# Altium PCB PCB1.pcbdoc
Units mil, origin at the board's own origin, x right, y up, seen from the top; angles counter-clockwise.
Board outline 8195 x 5475 mil, 2 copper layers (Top Layer, Bottom Layer), stack 62.206 mil thick; 63 components, 65 nets, 212 pads, 6 vias.
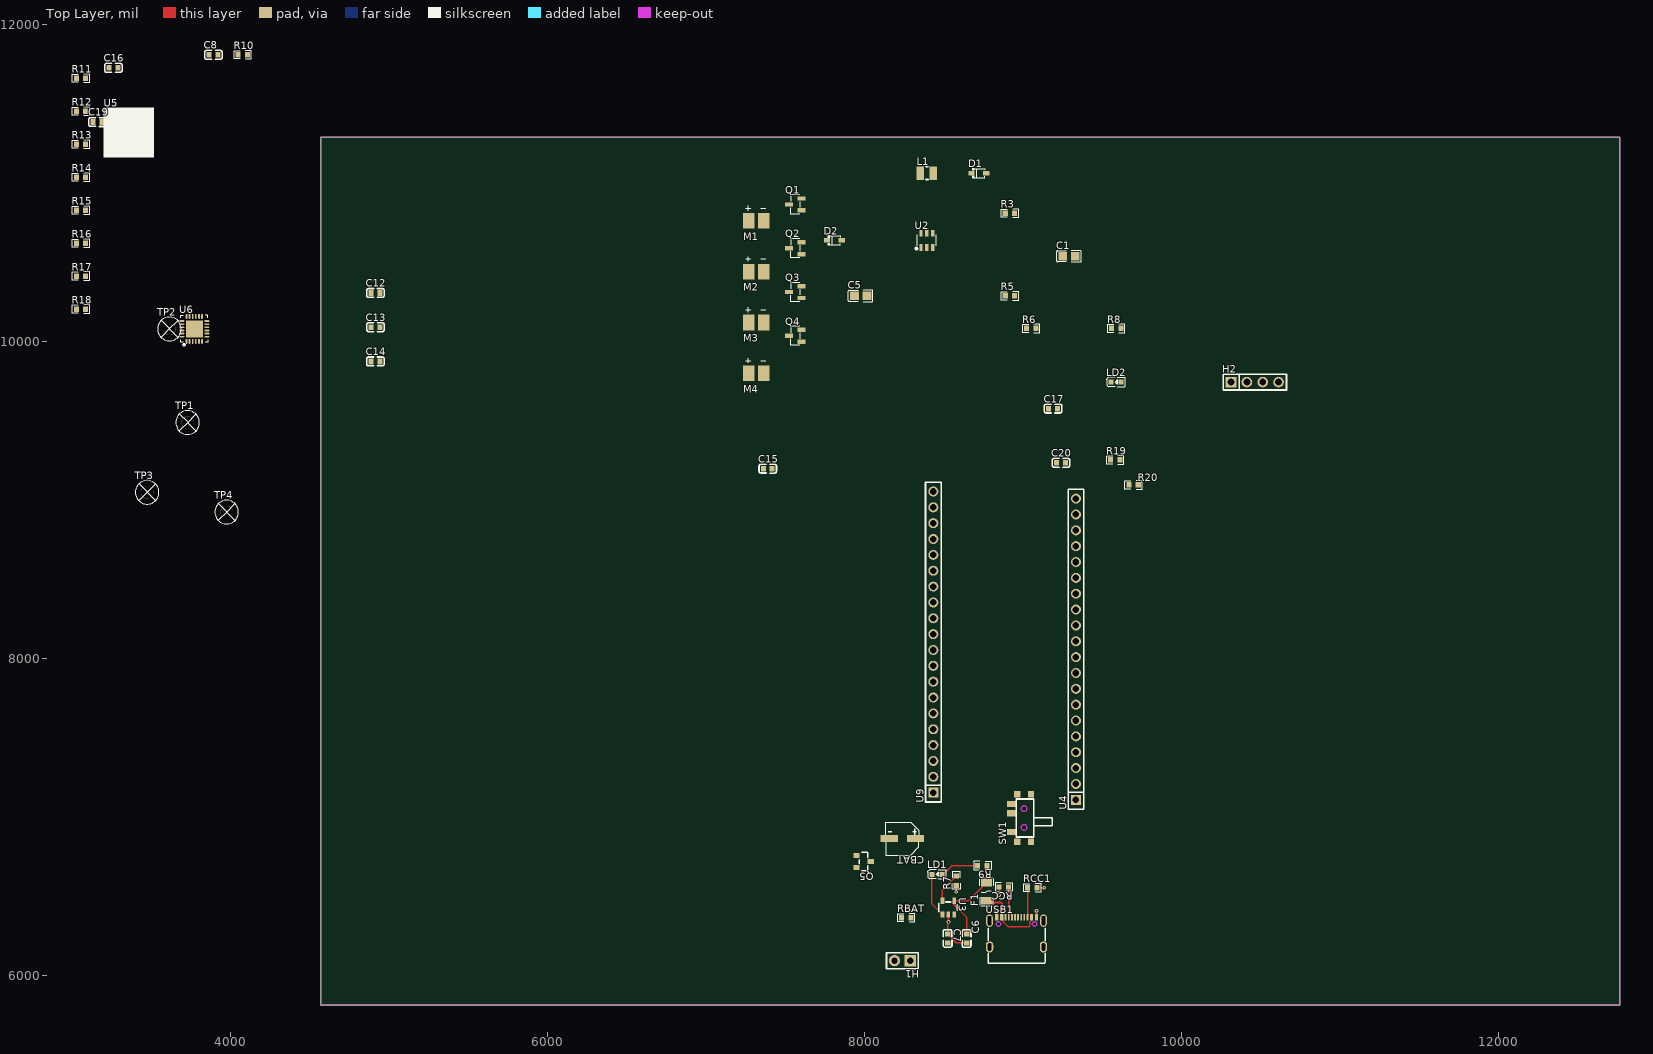
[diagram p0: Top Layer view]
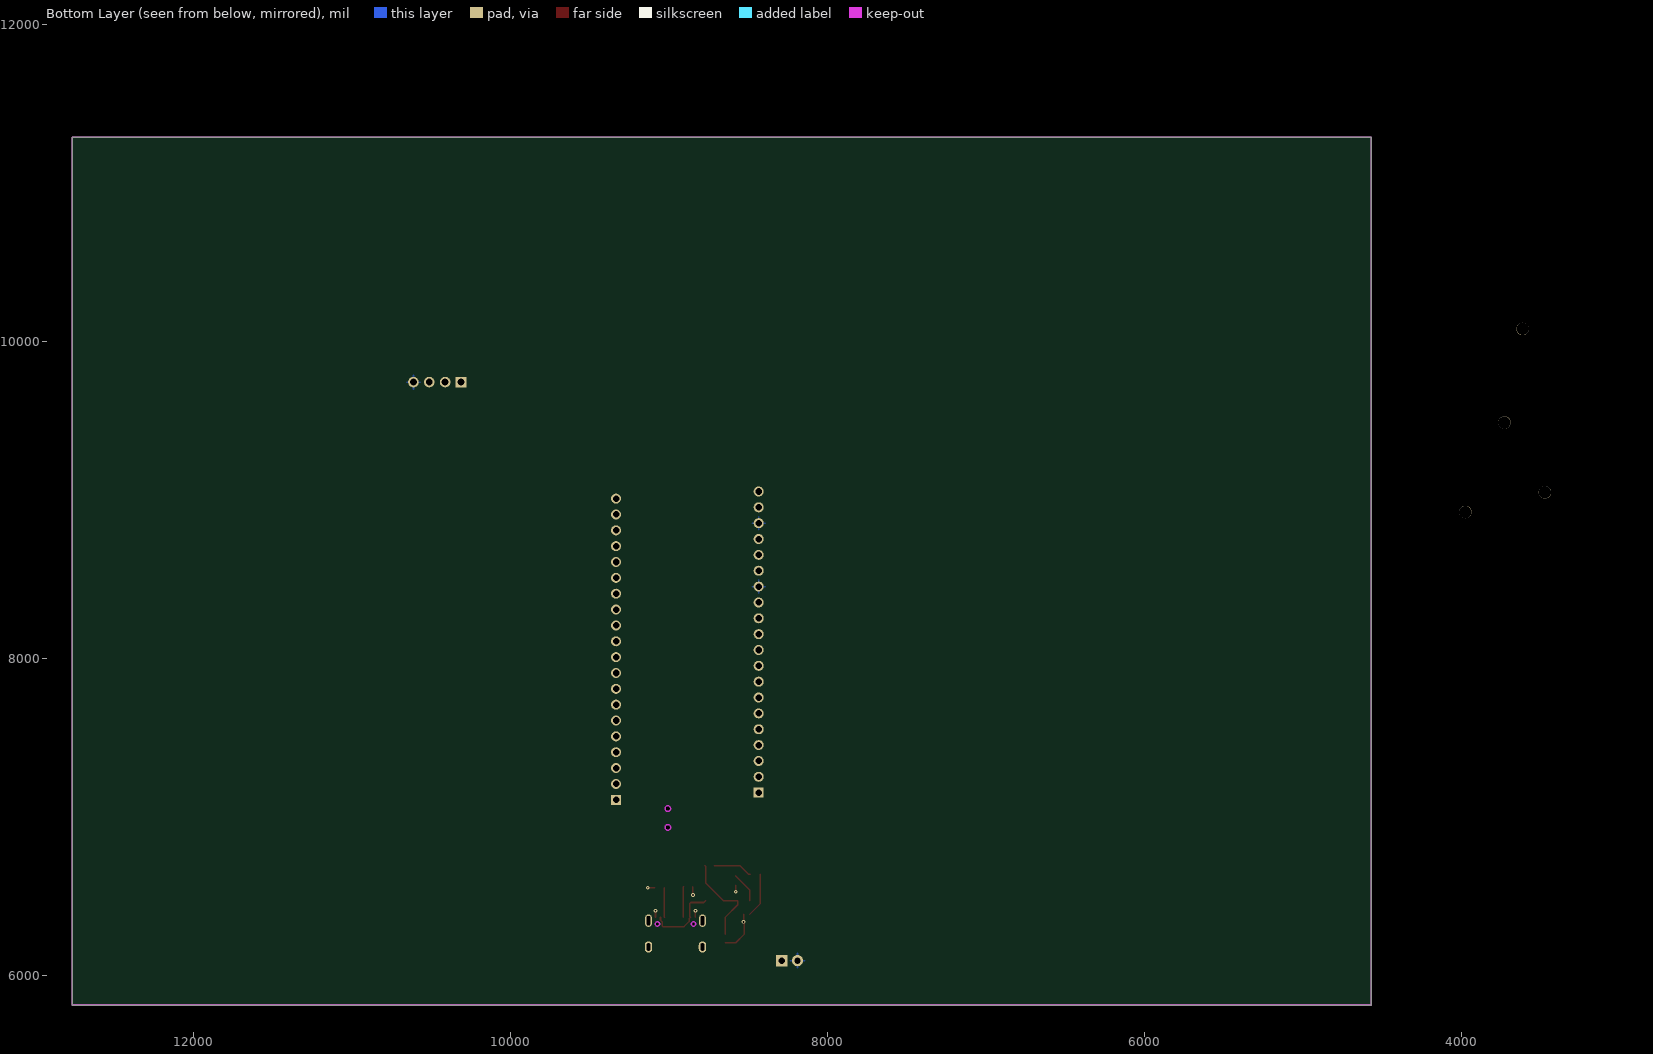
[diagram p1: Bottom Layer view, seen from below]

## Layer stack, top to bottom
Top Solder Mask Layer: solder mask 0.394, Dk 3.3
Top Layer: signal copper 1.379
Dielectric1: surface 59.449, FR4, Dk 4.5
Bottom Layer: signal copper 1.378
Bottom Solder Mask Layer: solder mask 0.394, Dk 3.3

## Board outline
4566.53,11290 4566.53,5815 12761.53,5815 12761.53,11290

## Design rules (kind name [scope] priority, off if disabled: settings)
BoardOutlineClearance copperThickness2oz_1 [All] p2 off: genericclearance=7.99 ignorepadtopadclearanceinfootprint=FALSE except(0: Arc-SplitContinuation Track-SplitContinuation SMDPad-SplitContinuation THPad-SplitContinuation Via-SplitContinuation Fill-SplitContinuation Region-SplitContinuation Poly-SplitContinuation Text-SplitContinuation Hole-SplitContinuation; 5.98: Arc-CutoutEdge SMDPad-CutoutEdge THPad-CutoutEdge Via-CutoutEdge Fill-CutoutEdge Region-CutoutEdge Text-CutoutEdge; 6.93: Hole-OutlineEdge Hole-CutoutEdge; 10: Poly-OutlineEdge Poly-CutoutEdge; 11.81: Arc-OutlineEdge Track-OutlineEdge SMDPad-OutlineEdge THPad-OutlineEdge Via-OutlineEdge Fill-OutlineEdge Region-OutlineEdge Text-OutlineEdge Track-CutoutEdge)
BoardOutlineClearance copperThickness1oz_1 [All] p4: genericclearance=4.02 ignorepadtopadclearanceinfootprint=FALSE except(0: Arc-SplitContinuation Track-SplitContinuation SMDPad-SplitContinuation THPad-SplitContinuation Via-SplitContinuation Fill-SplitContinuation Region-SplitContinuation Poly-SplitContinuation Text-SplitContinuation Hole-SplitContinuation; 6: SMDPad-CutoutEdge THPad-CutoutEdge Via-CutoutEdge Fill-CutoutEdge Region-CutoutEdge Text-CutoutEdge; 6.93: Hole-OutlineEdge Hole-CutoutEdge; 10: Poly-OutlineEdge Poly-CutoutEdge; 11.8: Arc-OutlineEdge Track-OutlineEdge SMDPad-OutlineEdge THPad-OutlineEdge Via-OutlineEdge Fill-OutlineEdge Region-OutlineEdge Text-OutlineEdge; 11.81: Arc-CutoutEdge Track-CutoutEdge)
Clearance copperThickness2oz [All] p1 off: gap=7.99 ignorepadtopadclearanceinfootprint=FALSE except(5.98: SMDPad-Track SMDPad-SMDPad THPad-Track SMDPad-THPad THPad-THPad Track-Via SMDPad-Via THPad-Via Via-Via Fill-Track Region-Track Fill-SMDPad Region-SMDPad Fill-THPad Region-THPad Fill-Via Region-Via Fill-Fill Fill-Region Region-Region Arc-Track Arc-SMDPad Arc-THPad Arc-Via Fill-Arc Region-Arc Arc-Arc Text-Track SMDPad-Text Text-THPad Text-Via Fill-Text Region-Text Arc-Text Text-Text; 6.93: Hole-Track Hole-SMDPad Hole-THPad Hole-Via Fill-Hole Region-Hole Hole-Arc Hole-Text; 10: Poly-Track Poly-SMDPad Poly-THPad Poly-Via Poly-Fill Poly-Region Poly-Poly Poly-Arc Poly-Text Poly-Hole)
Clearance copperThickness1oz [All] p3: gap=4.02 ignorepadtopadclearanceinfootprint=FALSE except(5.98: SMDPad-Track SMDPad-SMDPad THPad-Track SMDPad-THPad THPad-THPad Track-Via SMDPad-Via THPad-Via Via-Via Fill-Track Region-Track Fill-SMDPad Region-SMDPad Fill-THPad Region-THPad Fill-Via Region-Via Fill-Fill Fill-Region Region-Region; 6: Arc-Track Arc-SMDPad Arc-THPad Arc-Via Fill-Arc Region-Arc Arc-Arc Text-Track SMDPad-Text Text-THPad Text-Via Fill-Text Region-Text Arc-Text Text-Text; 6.93: Hole-Track Hole-SMDPad Hole-THPad Hole-Via Fill-Hole Region-Hole Hole-Arc Hole-Text; 10: Poly-Track Poly-SMDPad Poly-THPad Poly-Via Poly-Fill Poly-Region Poly-Poly Poly-Arc Poly-Text Poly-Hole)
Creepage creepage [All] p1: checkdistance=0 ignoreinternallayers=TRUE applytopolygonpour=TRUE
DiffPairsRouting differentialPair [All] p1: maxlimit=6 minlimit=6 mostfreqgap=6 toplayer_minwidth=5 toplayer_prefwidth=10 toplayer_maxwidth=100 toplayer_mingap=6 toplayer_prefgap=6 toplayer_maxgap=6 bottomlayer_minwidth=5 bottomlayer_prefwidth=10 bottomlayer_maxwidth=100 bottomlayer_mingap=6 bottomlayer_prefgap=6 bottomlayer_maxgap=6 maxuncoupledlength=10
HoleToHoleClearance otherClearance [All] p1: gap=11.81 allowstackedmicrovias=TRUE
Length netLength [All] p1: minlimit=0 maxlimit=0
MatchedLengths netLengthTolerance [All] p1: tolerance=1000
PasteMaskExpansion pasteMaskExpansion [All] p1: expansion=0
PlaneConnect innerPlane [All] p1: planeconnectstyle=Relief reliefexpansion=20 reliefentries=4 reliefconductorwidth=10 reliefairgap=10
PolygonConnect copperRegion [(InNet('GND'))] p1: connectstyle=Relief reliefconductorwidth=10 reliefentries=4 polygonreliefangle="90 Angle" airgapwidth=10 via.connectstyle=Relief via.reliefconductorwidth=10 via.reliefentries=4 via.polygonreliefangle="90 Angle" via.airgapwidth=10
RoutingVias viaSize [All] p1: holewidth=12.01 width=24.02 viastyle="Through Hole" minholewidth=11.81 minwidth=19.68 maxholewidth=248.03 maxwidth=393.7
SolderMaskExpansion solderMaskExpansion [IsVia] p1: expansion=-1000 istentingtop=TRUE
SolderMaskExpansion solderMaskExpansion [All] p2: expansion=2 istentingtop=FALSE
Width copperThickness2oz_2 [All] p1 off: maxlimit=100 minlimit=8 preferedwidth=10
Width copperThickness1oz_2 [All] p2: maxlimit=100 minlimit=5 preferedwidth=10

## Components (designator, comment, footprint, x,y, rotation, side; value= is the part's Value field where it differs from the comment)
C1 "22uF" C0805 9287.35,10539.06 r0 top
C5 "22uF" C0805 7973.57,10289.06 r0 top
C6 "4.7uF" C0603 8641.53,6235 r90 top
C7 "10uF" C0603 8521.53,6235 r270 top
C8 "100nF" C0603 3890.05,11809.78 r0 top
C12 "4.7uF" C0603 4912.48,10307.56 r0 top
C13 "4.7uF" C0603 4912.48,10091.44 r0 top
C14 "4.7uF" C0603 4912.48,9875.32 r0 top
C15 "4.7uF" C0603 7387.48,9199.2 r0 top
C16 "100nF" C0603 3258.9,11727.92 r0 top
C17 "100nF" C0603 9187.35,9577.92 r0 top
C19 "10nF" C0603 3158.9,11385.9 r0 top
C20 "2.2nF" C0603 9237.35,9235.9 r0 top
CBAT "10uF" CAP-SMD_BD5.0-L5.3-W5.3-LS6.0-FD 8236.53,6865 r180 top
D1 "1N5819WS" SOD-323_L1.8-W1.3-LS2.5-RD 8719.18,11063.15 r0 top
D2 "1N5819WS" SOD-323_L1.8-W1.3-LS2.5-RD 7807.73,10639.06 r0 top
F1 "JK-nSMD100/16V" F1206 8766.53,6530 r90 top
H1 "" HDR-TH_2P-P2.54-V-M-1 8236.53,6095 r180 top
H2 "" HDR-TH_4P-P2.54-V-M 10459.63,9745.28 r0 top
L1 "10uH" IND-SMD_L2.5-W2.0 8390.8,11063.15 r0 top
LD1 "" LED_0603 8456.53,6640 r0 top
LD2 "" LED_0603 9585.63,9745.28 r0 top
M1 "8520" 8520电机接口 7314.21,10762.64 r0 top
M2 "8520" 8520电机接口 7314.21,10441.99 r0 top
M3 "8520" 8520电机接口 7314.21,10121.34 r0 top
M4 "8520" 8520电机接口 7314.21,9800.69 r0 top
Q1 "SI2302" SOT-23-3_L2.9-W1.3-P1.90-LS2.4-BR 7560.86,10865.74 r0 top
Q2 "SI2302" SOT-23-3_L2.9-W1.3-P1.90-LS2.4-BR 7560.86,10589.57 r0 top
Q3 "SI2302" SOT-23-3_L2.9-W1.3-P1.90-LS2.4-BR 7560.86,10313.39 r0 top
Q4 "SI2302" SOT-23-3_L2.9-W1.3-P1.90-LS2.4-BR 7560.86,10037.22 r0 top
Q5 "AO3401A" SOT-23_L2.9-W1.3-P1.90-LS2.4-BR 7991.53,6720 r180 top
R3 "75kΩ" R0603 8915.05,10809.77 r0 top
R5 "10K" R0603 8915.05,10289.06 r0 top
R6 "200K" R0603 9049.79,10083.66 r0 top
R7 "2K" R0603 8576.53,6600 r90 top
R8 "10K" R0603 9585.63,10083.66 r0 top
R9 "10K" R0603 8741.53,6695 r180 top
R10 "100K" R0603 4074.79,11809.78 r0 top
R11 "100" R0603 3054.53,11661.86 r0 top
R12 "100" R0603 3054.53,11453.85 r0 top
R13 "100" R0603 3054.53,11245.83 r0 top
R14 "100" R0603 3054.53,11037.82 r0 top
R15 "10K" R0603 3054.53,10829.8 r0 top
R16 "10K" R0603 3054.53,10621.78 r0 top
R17 "10K" R0603 3054.53,10413.77 r0 top
R18 "10K" R0603 3054.53,10205.75 r0 top
R19 "4.7K" R0603 9579.87,9254.25 r0 top
R20 "4.7K" R0603 9694.87,9096.55 r0 top
RBAT "100K" R0603 8261.53,6365 r0 top
RCC "5.1K" R0603 8876.53,6560 r180 top
RCC1 "5.1K" R0603 9056.53,6555 r0 top
SW1 "SK-3296S-01-L1" SW-SMD_3P-P1.50_L2.7-W6.6 8986.53,6995 r90 top
TP1 "" M2螺丝 3726.53,9490 r0 top
TP2 "" M2螺丝 3612.47,10080.27 r0 top
TP3 "" M2螺丝 3471.53,9050 r0 top
TP4 "" M2螺丝 3972.98,8925.27 r0 top
U2 "MT3608" SOT-23-6_L2.9-W1.6-P0.95-LS2.8-BL 8390.8,10639.06 r0 top
U3 "LTH7" SOT-23-5_L2.9-W1.6-P0.95-LS2.8-BR 8526.53,6430 r270 top
U4 "排针左" HDR-TH_LAIL-PM2.54-20P-L 9331.53,8060 r90 top
U5 "" JLC-QRCODE-8x8 3356.53,11320 r0 top
U6 "MPU-6050" QFN-24_L4.0-W4.0-P0.50-BL-EP2.7 3769.18,10081.07 r0 top
U9 "排针右" HDR-TH_LAIL-PM2.54-20P-L 8431.53,8105 r90 top
USB1 "TYPE-C 16PIN 2MD(073)" USB-C-SMD_TYPE-C-6PIN-2MD-073 8956.53,6275 r0 top

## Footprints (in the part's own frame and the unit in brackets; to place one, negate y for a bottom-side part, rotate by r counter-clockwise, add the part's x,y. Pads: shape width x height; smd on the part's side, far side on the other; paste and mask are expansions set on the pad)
8520电机接口 [mm]
  rect 1.8x2.5 smd: 1(-1.2,0) 2(1.2,0)
  silkscreen extent -1.65,1.65 1.51,2.41
C0603 [mm]
  rect 0.8x0.9 smd: 1(-0.7,0) 2(0.7,0)
  silkscreen extent -1.41,-0.71 1.39,0.72
C0805 [mm]
  rect 1.41x1.35 smd paste-100 mask+0.051: 1(-1,0) 2(1,0)
  silkscreen extent -1.96,-0.9 1.96,0.9
CAP-SMD_BD5.0-L5.3-W5.3-LS6.0-FD [mm]
  rect 2.8x1.1 smd: 1(-2.1,0) 2(2.1,0)
  silkscreen extent -2.66,-2.62 2.66,2.65
F1206 [mm]
  rect 1.19x1.728 smd: 1(-1.445,0) 2(1.445,0)
  silkscreen extent -2.27,-1.09 2.27,1.09
HDR-TH_2P-P2.54-V-M-1 [mm]
  rect 1.8x1.8 hole 1: 1(-1.27,0)
  round 1.8 hole 1: 2(1.27,0)
  silkscreen extent -2.54,-1.27 2.54,1.27
HDR-TH_4P-P2.54-V-M [mm]
  rect 1.7x1.7 hole 1.1: 1(-3.81,0)
  round 1.7 hole 1.1: 2(-1.27,0) 3(1.27,0) 4(3.81,0)
  silkscreen extent -5.08,-1.27 5.08,1.27
HDR-TH_LAIL-PM2.54-20P-L [mm]
  rect 1.6x1.6 hole 1.05 paste+0 mask+0.051: 1(-24.13,0)
  round 1.6 hole 1.05 paste+0 mask+0.051: 2(-21.59,0) 3(-19.05,0) 4(-16.51,0) 5(-13.97,0) 6(-11.43,0) 7(-8.89,0) 8(-6.35,0) 9(-3.81,0) 10(-1.27,0) 11(1.27,0) 12(3.81,0) 13(6.35,0) 14(8.89,0) 15(11.43,0) 16(13.97,0) 17(16.51,0) 18(19.05,0) 19(21.59,0) 20(24.13,0)
  silkscreen extent -25.63,-1.25 25.64,1.25
IND-SMD_L2.5-W2.0 [mm]
  rect 1.2x2.2 smd: 1(1.028,0) 2(-1.028,0)
  silkscreen extent -0.2,-1.02 0.2,1.02
JLC-QRCODE-8x8 [mil]
  silkscreen extent -157,-157 157,157
LED_0603 [mil]
  rect 31.5x31.5 smd paste+0 mask+2: 1(-33.5,-0.4) 2(29.5,-0.2)
  silkscreen extent -61,-30 53,30
M2螺丝 [mm]
  round 2 hole 2: 1(0,0)
  silkscreen extent -1.9,-1.9 1.9,1.9
QFN-24_L4.0-W4.0-P0.50-BL-EP2.7 [mm]
  oval 0.28x0.8 smd paste-100 mask+0.05: 1(-1.25,-2) 2(-0.75,-2) 3(-0.25,-2) 4(0.25,-2) 5(0.75,-2) 6(1.25,-2) 13(1.25,2) 14(0.75,2) 15(0.25,2) 16(-0.25,2) 17(-0.75,2) 18(-1.242,2)
  oval 0.8x0.28 smd paste-100 mask+0.05: 7(2,-1.25) 8(2,-0.75) 9(2,-0.25) 10(2,0.25) 11(2,0.75) 12(2,1.25) 19(-2,1.25) 20(-2,0.75) 21(-2,0.25) 22(-2,-0.25) 23(-2,-0.75) 24(-2,-1.25)
  rect 2.7x2.7 smd paste-100 mask+0.05: 25(0.012,0)
  silkscreen extent -2.14,-2.79 2.16,2.15
R0603 [mil]
  rect 31.75x34.02 smd paste-3937.01 mask+2: 1(-29.66,0) 2(29.66,0)
  silkscreen extent -55,-26 55,26
SOD-323_L1.8-W1.3-LS2.5-RD [mm]
  rect 1x0.75 smd: 1(-1.173,0) 2(1.173,0)
  silkscreen extent -1.08,-0.8 0.9,0.8
SOT-23-3_L2.9-W1.3-P1.90-LS2.4-BR [mm]
  rect 1.25x0.7 smd: 1(1,-0.95) 2(1,0.95) 3(-1,0)
  silkscreen extent -0.73,-1.53 0.73,1.53
SOT-23-5_L2.9-W1.6-P0.95-LS2.8-BR [mm]
  rect 1x0.6 smd paste+0 mask+0.05: 1(1.1,-0.95) 2(1.1,0) 3(1.1,0.95) 4(-1.1,0.95) 5(-1.1,-0.95)
  silkscreen extent -0.89,-1.52 0.7,1.4
SOT-23-6_L2.9-W1.6-P0.95-LS2.8-BL [mil]
  rect 20.95x42.2 smd: 1(-37.4,-45.24) 2(0,-45.24) 3(37.4,-45.24) 4(37.4,45.24) 5(0,45.24) 6(-37.4,45.24)
  silkscreen extent -72,-57 61,35
SOT-23_L2.9-W1.3-P1.90-LS2.4-BR [mm]
  rect 1x0.8 smd: 1(1.15,-0.95) 2(1.15,0.95) 3(-1.15,0)
  silkscreen extent -0.7,-1.5 0.7,1.5
SW-SMD_3P-P1.50_L2.7-W6.6 [mm]
  rect 1x1 smd: 0(-3.8,-1.559) 0(-3.8,0.641) 0(3.8,-1.559) 0(3.8,0.641)
  rect 1x1.4 smd: 1(-2.25,1.559) 2(0.75,1.559) 3(2.25,1.559)
  Board Outline Layer circle w0.003: c-1.5,-0.459 r0.45
  Board Outline Layer circle w0.003: c1.5,-0.459 r0.45
  Board Outline Layer region: -1.5,-0.909 -1.695,-0.864 -1.852,-0.74 -1.939,-0.559 -1.939,-0.359 -1.852,-0.178 -1.695,-0.054 -1.5,-0.009 -1.5,-0.009 -1.305,-0.054 -1.148,-0.178 -1.061,-0.359 -1.061,-0.559 -1.148,-0.74 -1.305,-0.864 -1.5,-0.909
  Board Outline Layer region: -1.5,-0.909 -1.593,-0.899 -1.683,-0.87 -1.764,-0.823 -1.834,-0.76 -1.89,-0.684 -1.928,-0.598 -1.947,-0.506 -1.947,-0.412 -1.928,-0.32 -1.89,-0.234 -1.834,-0.158 -1.764,-0.095 -1.683,-0.048 -1.593,-0.019 -1.5,-0.009 -1.406,-0.019 -1.317,-0.048 -1.235,-0.095 -1.165,-0.158 -1.11,-0.234 -1.072,-0.32 -1.052,-0.412 -1.052,-0.506 -1.072,-0.598 -1.11,-0.684 -1.165,-0.76 -1.235,-0.823 -1.317,-0.87 -1.406,-0.899
  Board Outline Layer region: 1.5,-0.909 1.305,-0.864 1.148,-0.74 1.061,-0.559 1.061,-0.359 1.148,-0.178 1.305,-0.054 1.5,-0.009 1.5,-0.009 1.695,-0.054 1.852,-0.178 1.939,-0.359 1.939,-0.559 1.852,-0.74 1.695,-0.864 1.5,-0.909
  Board Outline Layer region: 1.5,-0.909 1.407,-0.899 1.317,-0.87 1.236,-0.823 1.166,-0.76 1.11,-0.684 1.072,-0.598 1.053,-0.506 1.053,-0.412 1.072,-0.32 1.11,-0.234 1.166,-0.158 1.236,-0.095 1.317,-0.048 1.407,-0.019 1.5,-0.009 1.594,-0.019 1.683,-0.048 1.765,-0.095 1.835,-0.158 1.89,-0.234 1.928,-0.32 1.948,-0.412 1.948,-0.506 1.928,-0.598 1.89,-0.684 1.835,-0.76 1.765,-0.823 1.683,-0.87 1.594,-0.899
  Multi-Layer board cut-out: -1.5,-0.909 -1.695,-0.864 -1.852,-0.74 -1.939,-0.559 -1.939,-0.359 -1.852,-0.178 -1.695,-0.054 -1.5,-0.009 -1.5,-0.009 -1.305,-0.054 -1.148,-0.178 -1.061,-0.359 -1.061,-0.559 -1.148,-0.74 -1.305,-0.864 -1.5,-0.909
  Multi-Layer board cut-out: 1.5,-0.909 1.305,-0.864 1.148,-0.74 1.061,-0.559 1.061,-0.359 1.148,-0.178 1.305,-0.054 1.5,-0.009 1.5,-0.009 1.695,-0.054 1.852,-0.178 1.939,-0.359 1.939,-0.559 1.852,-0.74 1.695,-0.864 1.5,-0.909
  silkscreen extent -3.05,-4.98 3.05,0.81
USB-C-SMD_TYPE-C-6PIN-2MD-073 [mm]
  rect 0.55x1.1 smd paste-100 mask+0.05: 1(-3.2,2.375) 2(-2.4,2.375) 11(2.4,2.375) 12(3.2,2.375)
  rect 0.3x1.1 smd paste-100 mask+0.05: 3(-1.75,2.375) 4(-1.25,2.375) 5(-0.75,2.375) 6(-0.25,2.375) 7(0.25,2.375) 8(0.75,2.375) 9(1.25,2.375) 10(1.75,2.375)
  oval 1.2x1.8 hole 0.6 slot 1.2 at 90 deg paste+0 mask+0.05: 13(-4.325,-2.375) 14(4.325,-2.375)
  oval 1.1x2 hole 0.6 slot 1.5 at 90 deg paste+0 mask+0.05: 13(-4.325,1.825) 14(4.325,1.825)
  Board Outline Layer circle w0.003: c-2.89,1.305 r0.35
  Board Outline Layer circle w0.003: c2.89,1.305 r0.35
  Board Outline Layer region: -2.54,1.305 -2.575,1.153 -2.672,1.031 -2.812,0.964 -2.968,0.964 -3.108,1.031 -3.205,1.153 -3.24,1.305 -3.24,1.305 -3.205,1.457 -3.108,1.579 -2.968,1.646 -2.812,1.646 -2.672,1.579 -2.575,1.457 -2.54,1.305
  Board Outline Layer region: -2.54,1.305 -2.549,1.227 -2.575,1.153 -2.616,1.087 -2.672,1.031 -2.738,0.99 -2.812,0.964 -2.89,0.955 -2.968,0.964 -3.042,0.99 -3.108,1.031 -3.164,1.087 -3.205,1.153 -3.231,1.227 -3.24,1.305 -3.231,1.383 -3.205,1.457 -3.164,1.523 -3.108,1.579 -3.042,1.62 -2.968,1.646 -2.89,1.655 -2.812,1.646 -2.738,1.62 -2.672,1.579 -2.616,1.523 -2.575,1.457 -2.549,1.383
  Board Outline Layer region: 3.24,1.305 3.205,1.153 3.108,1.031 2.968,0.964 2.812,0.964 2.672,1.031 2.575,1.153 2.54,1.305 2.54,1.305 2.575,1.457 2.672,1.579 2.812,1.646 2.968,1.646 3.108,1.579 3.205,1.457 3.24,1.305
  Board Outline Layer region: 3.24,1.305 3.231,1.227 3.205,1.153 3.164,1.087 3.108,1.031 3.042,0.99 2.968,0.964 2.89,0.955 2.812,0.964 2.738,0.99 2.672,1.031 2.616,1.087 2.575,1.153 2.549,1.227 2.54,1.305 2.549,1.383 2.575,1.457 2.616,1.523 2.672,1.579 2.738,1.62 2.812,1.646 2.89,1.655 2.968,1.646 3.042,1.62 3.108,1.579 3.164,1.523 3.205,1.457 3.231,1.383
  Multi-Layer board cut-out: -2.54,1.305 -2.575,1.153 -2.672,1.031 -2.812,0.964 -2.968,0.964 -3.108,1.031 -3.205,1.153 -3.24,1.305 -3.24,1.305 -3.205,1.457 -3.108,1.579 -2.968,1.646 -2.812,1.646 -2.672,1.579 -2.575,1.457 -2.54,1.305
  Multi-Layer board cut-out: 3.24,1.305 3.205,1.153 3.108,1.031 2.968,0.964 2.812,0.964 2.672,1.031 2.575,1.153 2.54,1.305 2.54,1.305 2.575,1.457 2.672,1.579 2.812,1.646 2.968,1.646 3.108,1.579 3.205,1.457 3.24,1.305
  silkscreen extent -4.5,-4.97 4.57,0.6

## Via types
v1: diameter 24.02, hole 12, Top Layer to Bottom Layer, 6 vias

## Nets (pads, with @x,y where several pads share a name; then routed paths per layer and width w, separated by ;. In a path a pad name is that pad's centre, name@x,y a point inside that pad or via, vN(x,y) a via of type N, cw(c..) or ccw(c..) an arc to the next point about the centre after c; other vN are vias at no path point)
$1N219: CBAT.1 SW1.3
$1N229: RCC1.1 USB1.10 | length 187.1
  Top Layer w10: USB1.10 9026.87,6369.94 RCC1.1
$1N230: RCC.1 USB1.4 | length 192
  Top Layer w10: RCC.1 8907.32,6558.86 USB1.4
$1N235: U9.1
$1N236: U9.3
$1N237: U9.2
$1N238: U9.8
$1N239: U9.9
$1N240: U9.10
$1N242: U9.12
$1N243: U9.13
$1N247: U9.20
$1N248: U4.1
$1N249: U4.2
$1N250: U4.3
$1N251: U4.4
$1N252: U4.5
$1N253: U4.6
$1N254: U4.7
$1N255: U4.8
$1N256: U4.9
$1N257: U4.10
$1N260: U4.13
$1N261: U4.14
$1N262: U4.15
$1N263: U4.16
$1N264: U4.17
$1N265: U4.18
$1N266: U4.19
$1N267: U4.20
$1N270: C5.2 D2.1 L1.2 U2.4 U2.5
$1N273: LD2.2 R8.1
$1N277: R7.2 U3.5 | length 192.6
  Top Layer w10: U3.5 8489.12,6542.26 R7.2
$1N285: LD1.2 R9.2 | length 248.7
  Top Layer w10: LD1.2 8496.33,6639.8 8551.53,6695 R9.2
$1N286: LD1.1 U3.1 | length 280.3
  Top Layer w10: LD1.1 8423.03,6452.8 U3.1
$1N292: C20.1 U6.20
$1N296: C16.2 U6.10
$1N300: R3.1 R5.2 U2.3
$1N301: D1.2 L1.1 U2.1
$1N306: F1.1 USB1.2 USB1.11 | length 469.3
  Top Layer w10: F1.1 8777.57,6462.07 8859.46,6462.07 8866.53,6455 8866.53,6372.99 USB1.2 8870.74,6359.8 8870.74,6342.3 8903.05,6310 9036.53,6310 9039.72,6313.19 9039.72,6339.05 9051.02,6350.35 USB1.11
$2N1: C12.1 M1.2 Q1.3
$2N5: C15.1 M4.2 Q4.3
$2N6: Q4.1 R14.1 R18.2
$2N10: C14.1 M3.2 Q3.3
$2N11: Q3.1 R13.1 R17.2
$2N15: C13.1 M2.2 Q2.3
$2N16: Q2.1 R12.1 R16.2
$2N20: Q1.1 R11.1 R15.2
+3.3V: C17.2 C19.2 H2.1 R8.2 R19.1 R20.1 U6.8 U6.13 U9.17
+5V: C1.2 D1.1 R3.2
BAT: C8.2 R6.1 R10.2 U9.11
GND: C1.1 C5.1 C6.1 C7.1 C8.1 C16.1 C17.1 C19.1 C20.2 H1.2 H2.4 Q1.2 Q2.2 Q3.2 Q4.2 R5.1 R7.1 R10.1 R15.1 R16.1 R17.1 R18.1 RCC1.2 RCC.2 SW1.0 SW1.2 U2.2 U3.2 U6.1 U6.9 U6.11 U6.18 U6.25 U9.14 U9.18 USB1.1 USB1.12 | length 487.7
  Top Layer w10: U3.2 v1(8526.53,6340) 8521.53,6335 C7.1 8576.65,6207.44 C6.1 ; v1(8576.53,6530) R7.1 ; USB1.1 v1(8830.54,6410) ; v1(8846.87,6510) RCC.2 ; USB1.12 v1(9082.51,6410) ; RCC1.2 v1(9131.53,6555)
IIC_SCL: R19.2 U4.11 U6.23
IIC_SDA: R20.2 U4.12 U6.24
LED: LD2.1
PWM1: R11.2 U9.7
PWM2: R12.2 U9.6
PWM3: R13.2 U9.5
PWM4: R14.2 U9.4
RXD4: H2.3
SW1: CBAT.2 Q5.1 RBAT.1
TXD4: H2.2
V+: C6.2 F1.2 R9.1 U3.4 | length 602.6
  Top Layer w10: C6.2 8641.53,6370 8563.93,6447.6 U3.4 8652.95,6473.31 F1.2 8766.53,6690.34 R9.1
VBAT: C7.2 H1.1 Q5.3 RBAT.2 U3.3
VBAT1: C12.2 C13.2 C14.2 C15.2 D2.2 M1.1 M2.1 M3.1 M4.1 Q5.2 R6.2
pads on no net: SW1.1 TP1.1 TP2.1 TP3.1 TP4.1 U2.6 U6.2 U6.3 U6.4 U6.5 U6.6 U6.7 U6.12 U6.14 U6.15 U6.16 U6.17 U6.19 U6.21 U6.22 U9.15 U9.16 U9.19 USB1.3 USB1.5 USB1.6 USB1.7 USB1.8 USB1.9 USB1.13 USB1.14

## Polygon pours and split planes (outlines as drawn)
GND on Bottom Layer (solid, remove dead copper, pour order 2): 4096.53,11015 4096.53,3000 15571.53,3000 15571.53,11015
GND on Bottom Layer (solid, remove dead copper, pour order 0): 4621.53,11300 4621.53,5815 12746.53,5815 12746.53,11300

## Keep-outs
Board Outline Layer:
  the board outline again, w10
